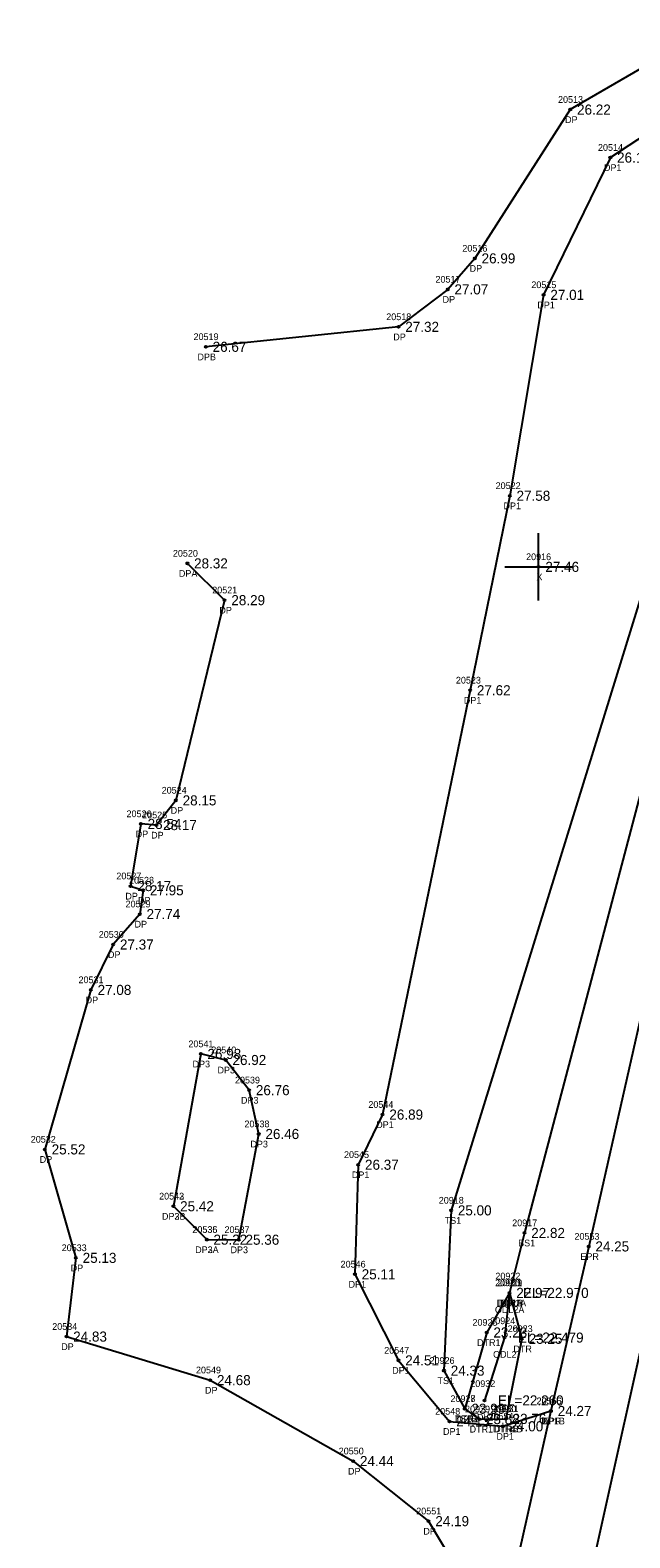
# Model space of a CAD drawing. Extents: x 2655177 to 2656219, y 761780 to 764748.
# Drawn here: x 2655478.9 to 2655568.1, y 762575 to 762799.3 of the extents above; entities that cross this region are included whole.
import ezdxf

# ---------------------------------------------------------------- set-up
doc = ezdxf.new("R2010")
doc.units = 0
for name, color, linetype in [('RD_DTM_BkLn1', 7, 'Continuous'), ('RD_DTM_BkLn2', 7, 'Continuous'), ('RD_DTM_BkLn_txCode', 7, 'Continuous'), ('RD_EX_Driveway', 7, 'Continuous'), ('RD_EX_Driveway_txCode', 7, 'Continuous'), ('RD_EX_H2O', 7, 'Continuous'), ('RD_EX_H2O_txCode', 7, 'Continuous'), ('RD_EX_Misc', 7, 'Continuous'), ('RD_EX_Misc_txCode', 7, 'Continuous'), ('RD_EX_Road', 7, 'Continuous'), ('RD_EX_Road_txCode', 7, 'Continuous'), ('RD_EX_TX_Driveway_ELEV', 7, 'Continuous'), ('RD_EX_TX_H2O_ELEV', 7, 'Continuous'), ('RD_EX_TX_Misc_ELEV', 7, 'Continuous'), ('RD_EX_TX_Road_ELEV', 7, 'Continuous'), ('RD_SMD_Locator', 7, 'Continuous')]:
    doc.layers.add(name, color=color, linetype=linetype)

msp = doc.modelspace()

# ---------------------------------------------------------------- linework, layer by layer
at = {"layer": 'RD_DTM_BkLn1'}
msp.add_lwpolyline([(2655711.06, 763230.3), (2655703.38, 763195.9), (2655681.97, 763099.65), (2655659.44, 762998.39), (2655637.72, 762903.26), (2655615.94, 762806.28), (2655593.94, 762710.45), (2655572.67, 762616.37), (2655551.12, 762519.58), (2655528.83, 762422.13), (2655507.58, 762326.81), (2655486.01, 762234.2), (2655464.77, 762141.12), (2655442.2, 762047.28), (2655420.99, 761952.95), (2655398.79, 761855.74), (2655384.11, 761791.21)], dxfattribs=at)
at = {"layer": 'RD_DTM_BkLn2'}
for points in [[(2655588.92, 762785.07), (2655578.49, 762783.94), (2655570.04, 762715.92), (2655541.51, 762623.69), (2655540.45, 762599.84), (2655543.53, 762594.17)], [(2655588.92, 762785.07), (2655577.48, 762715.28), (2655552.42, 762620.33), (2655550.2, 762611.41)]]:
    msp.add_lwpolyline(points, dxfattribs=at)
at = {"layer": 'RD_EX_Driveway'}
msp.add_line((2655505.16, 762619.33), (2655500.2, 762624.3), dxfattribs=at)
for points in [[(2655605, 762809.37), (2655586.47, 762798.41), (2655573.36, 762795.67), (2655559.24, 762787.47), (2655545.04, 762765.33), (2655541.01, 762760.72), (2655533.69, 762755.14), (2655505.04, 762752.17)], [(2655598.99, 762783.09), (2655591.74, 762789.45), (2655575.98, 762787.38), (2655565.19, 762780.33), (2655555.27, 762759.9), (2655550.24, 762730.01), (2655544.34, 762701.07), (2655531.32, 762637.94), (2655527.7, 762630.48), (2655527.21, 762614.18), (2655533.68, 762601.37), (2655541.26, 762592.29), (2655549.19, 762591.56), (2655556.36, 762593.84)], [(2655502.28, 762719.95), (2655507.82, 762714.48), (2655500.58, 762684.69), (2655497.67, 762681.01), (2655495.37, 762681.19), (2655493.84, 762671.94), (2655495.71, 762671.31), (2655495.21, 762667.77), (2655491.25, 762663.24), (2655487.93, 762656.49), (2655481.1, 762632.76), (2655485.71, 762616.62), (2655484.3, 762604.91), (2655505.68, 762598.43), (2655526.95, 762586.38), (2655538.16, 762577.45), (2655543.82, 762568.02), (2655548.11, 762557.14)], [(2655505.16, 762619.33), (2655509.93, 762619.32), (2655512.89, 762635.05), (2655511.47, 762641.57), (2655507.99, 762646.06), (2655504.27, 762646.96), (2655500.2, 762624.3)]]:
    msp.add_lwpolyline(points, dxfattribs=at)
at = {"layer": 'RD_EX_H2O'}
for points in [[(2655550.2, 762611.41), (2655546.8, 762605.52), (2655543.53, 762594.17), (2655545.69, 762592.63), (2655549.65, 762592.67)], [(2655550.2, 762611.41), (2655549.45, 762604.76), (2655546.48, 762595.41)], [(2655550.2, 762611.41), (2655552.04, 762604.58), (2655549.65, 762592.67)]]:
    msp.add_lwpolyline(points, dxfattribs=at)
at = {"layer": 'RD_EX_Misc'}
for p, q in [((2655554.52, 762714.43), (2655554.52, 762724.43)), ((2655549.52, 762719.43), (2655559.52, 762719.43))]:
    msp.add_line(p, q, dxfattribs=at)
at = {"layer": 'RD_EX_Road'}
msp.add_lwpolyline([(2655700.99, 763232.28), (2655693.55, 763198.57), (2655671.65, 763102.04), (2655649.04, 763001.06), (2655627.27, 762906.23), (2655605, 762809.37), (2655598.99, 762783.09), (2655583.65, 762714.14), (2655561.97, 762618.32), (2655556.36, 762593.84), (2655548.11, 762557.14), (2655540.1, 762522.48), (2655518.03, 762425.04), (2655496.48, 762329.56), (2655475.55, 762236.62), (2655473.2, 762226.14), (2655466.57, 762197.5), (2655460.06, 762168.16), (2655454.26, 762143.78), (2655432.5, 762049.88), (2655410.7, 761955.51), (2655388.17, 761858.43), (2655373.5, 761793.95)], dxfattribs=at)
at = {"layer": 'RD_SMD_Locator'}
for centre in [(2655559.24, 762787.47), (2655565.19, 762780.33), (2655545.04, 762765.33), (2655541.01, 762760.72), (2655555.27, 762759.9), (2655533.69, 762755.14), (2655505.04, 762752.17), (2655550.24, 762730.01), (2655502.28, 762719.95), (2655554.52, 762719.43), (2655507.82, 762714.48), (2655544.34, 762701.07), (2655500.58, 762684.69), (2655495.37, 762681.19), (2655497.67, 762681.01), (2655493.84, 762671.94), (2655495.71, 762671.31), (2655495.21, 762667.77), (2655491.25, 762663.24), (2655487.93, 762656.49), (2655504.27, 762646.96), (2655507.99, 762646.06), (2655511.47, 762641.57), (2655531.32, 762637.94), (2655512.89, 762635.05), (2655481.1, 762632.76), (2655527.7, 762630.48), (2655500.2, 762624.3), (2655500.2, 762624.3), (2655541.51, 762623.69), (2655505.16, 762619.33), (2655505.16, 762619.33), (2655509.93, 762619.32), (2655552.42, 762620.33), (2655485.71, 762616.62), (2655561.97, 762618.32), (2655527.21, 762614.18), (2655550.2, 762611.41), (2655550.2, 762611.41), (2655550.2, 762611.41), (2655550.2, 762611.41), (2655546.8, 762605.52), (2655484.3, 762604.91), (2655549.45, 762604.76), (2655552.04, 762604.58), (2655533.68, 762601.37), (2655505.68, 762598.43), (2655540.45, 762599.84), (2655543.53, 762594.17), (2655543.53, 762594.17), (2655546.48, 762595.41), (2655541.26, 762592.29), (2655545.69, 762592.63), (2655549.65, 762592.67), (2655549.65, 762592.67), (2655556.36, 762593.84), (2655556.36, 762593.84), (2655549.19, 762591.56), (2655526.95, 762586.38), (2655538.16, 762577.45)]:
    msp.add_circle(centre, 0.15, dxfattribs=at)

# ---------------------------------------------------------------- texts
at = {"layer": 'RD_DTM_BkLn_txCode'}
for s, p in [('20918', (2655539.67, 762624.69)), ('TS1', (2655540.55, 762621.69)), ('20917', (2655550.59, 762621.33)), ('BS1', (2655551.48, 762618.33)), ('20919', (2655548.37, 762612.41)), ('BS1B', (2655548.79, 762609.41)), ('20926', (2655538.3, 762600.84)), ('TS1', (2655539.49, 762597.84)), ('20927', (2655541.41, 762595.17)), ('TS1B', (2655542.1, 762592.17))]:
    msp.add_text(s, height=1, dxfattribs=at).set_placement(p)
at = {"layer": 'RD_EX_Driveway_txCode'}
for s, p in [('20513', (2655557.41, 762788.47)), ('DP', (2655558.46, 762785.47)), ('20514', (2655563.35, 762781.33)), ('DP1', (2655564.24, 762778.33)), ('20516', (2655543.18, 762766.33)), ('20517', (2655539.18, 762761.72)), ('DP', (2655544.26, 762763.33)), ('20515', (2655553.44, 762760.9)), ('DP', (2655540.24, 762758.72)), ('DP1', (2655554.33, 762757.9)), ('20518', (2655531.86, 762756.14)), ('20519', (2655503.2, 762753.17)), ('DP', (2655532.91, 762753.14)), ('DPB', (2655503.78, 762750.17)), ('20522', (2655548.13, 762731.01)), ('DP1', (2655549.3, 762728.01)), ('20520', (2655500.13, 762720.95)), ('DPA', (2655501.02, 762717.95)), ('20521', (2655505.98, 762715.48)), ('DP', (2655507.04, 762712.48)), ('20523', (2655542.22, 762702.07)), ('DP1', (2655543.4, 762699.07)), ('20524', (2655498.46, 762685.69)), ('20526', (2655493.23, 762682.19)), ('20525', (2655495.56, 762682.01)), ('DP', (2655499.8, 762682.69)), ('DP', (2655494.6, 762679.19)), ('DP', (2655496.89, 762679.01)), ('20527', (2655491.72, 762672.94)), ('20528', (2655493.6, 762672.31)), ('DP', (2655493.06, 762669.94)), ('20529', (2655493.09, 762668.77)), ('DP', (2655494.93, 762669.31)), ('DP', (2655494.43, 762665.77)), ('20530', (2655489.1, 762664.24)), ('DP', (2655490.47, 762661.24)), ('20531', (2655486.09, 762657.49)), ('DP', (2655487.15, 762654.49)), ('20541', (2655502.44, 762647.96)), ('20540', (2655505.83, 762647.06)), ('DP3', (2655503.05, 762644.96)), ('DP3', (2655506.76, 762644.06)), ('20539', (2655509.36, 762642.57)), ('DP3', (2655510.25, 762639.57)), ('20544', (2655529.2, 762638.94)), ('20538', (2655510.77, 762636.05)), ('DP1', (2655530.37, 762635.94)), ('20532', (2655478.99, 762633.76)), ('DP3', (2655511.66, 762633.05)), ('20545', (2655525.58, 762631.48)), ('DP', (2655480.32, 762630.76)), ('DP1', (2655526.75, 762628.48)), ('20542', (2655498.08, 762625.3)), ('20543', (2655498.08, 762625.3)), ('DP3B', (2655498.5, 762622.3)), ('DP2B', (2655498.5, 762622.3)), ('20536', (2655503.02, 762620.33)), ('20535', (2655503.04, 762620.33)), ('20537', (2655507.81, 762620.32)), ('20533', (2655483.59, 762617.62)), ('DP2A', (2655503.44, 762617.33)), ('DP3A', (2655503.44, 762617.33)), ('DP3', (2655508.7, 762617.32)), ('DP', (2655484.93, 762614.62)), ('20546', (2655525.07, 762615.18)), ('DP1', (2655526.26, 762612.18)), ('20534', (2655482.18, 762605.91)), ('DP', (2655483.52, 762602.91)), ('20547', (2655531.56, 762602.37)), ('20549', (2655503.56, 762599.43)), ('DP1', (2655532.74, 762599.37)), ('DP', (2655504.9, 762596.43)), ('20548', (2655539.14, 762593.29)), ('20555', (2655554.24, 762594.84)), ('20554', (2655547.07, 762592.56)), ('DP1B', (2655554.94, 762591.84)), ('DP1', (2655540.31, 762590.29)), ('DP1', (2655548.25, 762589.56)), ('20550', (2655524.79, 762587.38)), ('DP', (2655526.17, 762584.38)), ('20551', (2655536.32, 762578.45)), ('DP', (2655537.38, 762575.45))]:
    msp.add_text(s, height=1, dxfattribs=at).set_placement(p)
at = {"layer": 'RD_EX_H2O_txCode'}
for s, p in [('20922', (2655548.09, 762613.41)), ('20920', (2655548.05, 762612.41)), ('20921', (2655548.37, 762612.41)), ('DTR1A', (2655548.28, 762609.41)), ('DTRA', (2655548.45, 762609.41)), ('20925', (2655544.68, 762606.52)), ('20924', (2655547.33, 762606.76)), ('ODL2A', (2655548.02, 762608.41)), ('20923', (2655549.92, 762605.58)), ('DTR1', (2655545.37, 762603.52)), ('DTR', (2655550.77, 762602.58)), ('ODL2', (2655547.75, 762601.76)), ('20932', (2655544.36, 762597.41)), ('20928', (2655541.41, 762595.17)), ('20929', (2655543.58, 762593.63)), ('20930', (2655547.49, 762593.67)), ('20931', (2655547.81, 762593.67)), ('DTR1', (2655542.1, 762592.17)), ('ODL2B', (2655544.31, 762592.41)), ('DTR1', (2655544.26, 762590.63)), ('DTR1B', (2655547.74, 762590.67)), ('DTRB', (2655547.91, 762590.67))]:
    msp.add_text(s, height=1, dxfattribs=at).set_placement(p)
at = {"layer": 'RD_EX_Misc_txCode'}
for s, p in [('20916', (2655552.66, 762720.43)), ('X', (2655554.2, 762717.43))]:
    msp.add_text(s, height=1, dxfattribs=at).set_placement(p)
at = {"layer": 'RD_EX_Road_txCode'}
for s, p in [('20553', (2655559.85, 762619.32)), ('EPR', (2655560.74, 762616.32)), ('20556', (2655554.21, 762594.84)), ('EPR', (2655555.13, 762591.84))]:
    msp.add_text(s, height=1, dxfattribs=at).set_placement(p)
at = {"layer": 'RD_EX_TX_Driveway_ELEV'}
for s, p in [('26.22', (2655560.24, 762786.72)), ('26.15', (2655566.19, 762779.58)), ('26.99', (2655546.04, 762764.58)), ('27.07', (2655542.01, 762759.97)), ('27.01', (2655556.27, 762759.15)), ('27.32', (2655534.69, 762754.39)), ('26.67', (2655506.04, 762751.42)), ('27.58', (2655551.24, 762729.26)), ('28.32', (2655503.28, 762719.2)), ('28.29', (2655508.82, 762713.73)), ('27.62', (2655545.34, 762700.32)), ('28.15', (2655501.58, 762683.94)), ('28.54', (2655496.37, 762680.44)), ('28.17', (2655498.67, 762680.26)), ('28.17', (2655494.84, 762671.19)), ('27.95', (2655496.71, 762670.56)), ('27.74', (2655496.21, 762667.02)), ('27.37', (2655492.25, 762662.49)), ('27.08', (2655488.93, 762655.74)), ('26.98', (2655505.27, 762646.21)), ('26.92', (2655508.99, 762645.31)), ('26.76', (2655512.47, 762640.82)), ('26.89', (2655532.32, 762637.19)), ('26.46', (2655513.89, 762634.3)), ('25.52', (2655482.1, 762632.01)), ('26.37', (2655528.7, 762629.73)), ('25.42', (2655501.2, 762623.55)), ('25.42', (2655501.2, 762623.55)), ('25.22', (2655506.16, 762618.58)), ('25.22', (2655506.16, 762618.58)), ('25.36', (2655510.93, 762618.57)), ('25.13', (2655486.71, 762615.87)), ('25.11', (2655528.21, 762613.43)), ('24.83', (2655485.3, 762604.16)), ('24.51', (2655534.68, 762600.62)), ('24.68', (2655506.68, 762597.68)), ('24.27', (2655557.36, 762593.09)), ('24.13', (2655542.26, 762591.54)), ('24.00', (2655550.19, 762590.81)), ('24.44', (2655527.95, 762585.63)), ('24.19', (2655539.16, 762576.7))]:
    msp.add_text(s, height=1.5, dxfattribs=at).set_placement(p)
at = {"layer": 'RD_EX_TX_H2O_ELEV'}
for s, p in [('22.97', (2655551.2, 762610.66)), ('22.97', (2655551.2, 762610.66)), ('EL=22.970', (2655552.2, 762610.66)), ('23.23', (2655547.8, 762604.77)), ('EL=22.479', (2655551.45, 762604.01)), ('23.25', (2655553.04, 762603.83)), ('23.99', (2655544.53, 762593.42)), ('EL=22.260', (2655548.48, 762594.66)), ('23.88', (2655546.69, 762591.88)), ('23.76', (2655550.65, 762591.92)), ('23.76', (2655550.65, 762591.92))]:
    msp.add_text(s, height=1.5, dxfattribs=at).set_placement(p)
at = {"layer": 'RD_EX_TX_Misc_ELEV'}
for s, p in [('27.46', (2655555.52, 762718.68)), ('25.00', (2655542.51, 762622.94)), ('22.82', (2655553.42, 762619.58)), ('22.97', (2655551.2, 762610.66)), ('24.33', (2655541.45, 762599.09)), ('23.99', (2655544.53, 762593.42))]:
    msp.add_text(s, height=1.5, dxfattribs=at).set_placement(p)
at = {"layer": 'RD_EX_TX_Road_ELEV'}
for s, p in [('24.25', (2655562.97, 762617.57)), ('24.27', (2655557.36, 762593.09))]:
    msp.add_text(s, height=1.5, dxfattribs=at).set_placement(p)

doc.saveas('drawing.dxf')
